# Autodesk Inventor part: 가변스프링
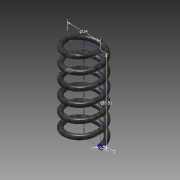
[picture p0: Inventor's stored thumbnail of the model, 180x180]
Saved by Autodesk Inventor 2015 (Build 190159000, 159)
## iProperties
Created: 2020-02
Part Number: 가변스프링
Material: 강철
Document SubType Name: Modeling
Designer: LINEART-A501-2
Density: 7.85 g/cm^3
Appearance: 플레이트
Mass: 6.43145 g
Surface Area: 16.623 cm^2
Volume: 0.819293 cm^3
Author: LINEART-A501-2
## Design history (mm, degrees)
sketch "스케치1"
  geometry: L1 (0, 0)-(-7, 0); L2 (-7, 0)-(-7, 35.5); L3 (-7, 35.5)-(0, 35.5); L4 (0, 35.5)-(0, 0); C1 r 1 at (-7, 0)
  constraints: 8 end point, 2 parallel, 1 centre point, 1 coincident, 1 horizontal, 1 perpendicular
  dimensions: "d3" = 14 diameter of L2 L4; "d5" = 2 diameter of C1; "d6" = 35.5 distance of L1.end L2.end (derived)
feature "코일1" sketch "스케치1" pitch "d7" = 10; turns "d9" = 6; dims "d8" = 35.5 (= d6), "d10" = 0, angle "d11" = 90 deg, angle "d12" = 90 deg, "d13" = 0, "d14" = 0
sketch "스케치2"
  geometry: L1 (8, 0)-(6, 0) reference; 1 further point
  constraints: 1 horizontal alignment
extrude "돌출1" cut sketch "스케치2" stored distance "d15" = 10; taper "d16" = 0 deg
sketch "스케치3"
  geometry: A1 r 1 centre (0, 0) between (-1, 0) and (1, 0) reference; 1 further point
  constraints: 1 horizontal alignment, 1 point on circle
node "작업 평면1"
sketch "스케치4"
  geometry: L1 (-2, 0)-(0, 0) reference; 1 further point
  constraints: 1 horizontal alignment
extrude "돌출2" cut sketch "스케치4" stored distance "d17" = 10; taper "d18" = 0 deg
node "솔리드1"
node "절단 모서리 투영1"
node "절단 모서리 투영2"
